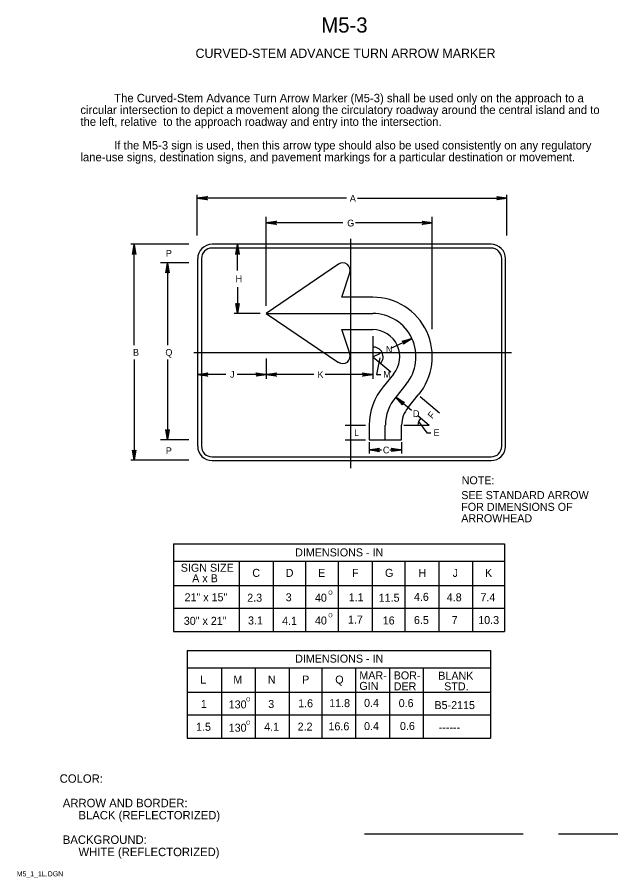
# Model space of a CAD drawing. Extents: x 0.5 to 7.5, y 0.2 to 10.2.
import ezdxf

# ---------------------------------------------------------------- set-up
doc = ezdxf.new("R2010")
doc.units = 0
for name, color, linetype in [('1', 7, 'Continuous'), ('2', 7, 'Continuous'), ('3', 7, 'Continuous')]:
    doc.layers.add(name, color=color, linetype=linetype)

# ---------------------------------------------------------------- blocks, each defined once
blk = doc.blocks.new('RARROW')
at = {"layer": '1'}
blk.add_lwpolyline([(-89.4, 11.2), (-86.1, 4.7), (0, 0), (-89.4, 11.2), (-94, 15.2), (0, 0), (-86, -4.3), (-89.2, -10.7), (0, 0), (-94, -14.9), (-89.2, -10.7)], dxfattribs=at)

msp = doc.modelspace()

# ---------------------------------------------------------------- linework, layer by layer
at = {"layer": '1'}
for p, q in [((4.545, 0.667), (6.395, 0.667)), ((6.809, 0.667), (7.5, 0.667))]:
    msp.add_line(p, q, dxfattribs=at)
at = {"layer": '2'}
for p, q in [((2.317, 4.054), (2.317, 3.032)), ((2.317, 4.054), (6.177, 4.054)), ((6.177, 4.056), (6.177, 3.032)), ((6.177, 3.849), (2.317, 3.849)), ((3.084, 3.848), (3.084, 3.03)), ((3.481, 3.849), (3.481, 3.032)), ((3.855, 3.849), (3.855, 3.032)), ((4.239, 3.849), (4.239, 3.032)), ((4.633, 3.849), (4.633, 3.032)), ((5.017, 3.849), (5.017, 3.032)), ((5.411, 3.849), (5.411, 3.032)), ((5.804, 3.849), (5.804, 3.032)), ((2.317, 3.57), (6.177, 3.57)), ((2.317, 3.304), (6.177, 3.304)), ((2.317, 3.032), (6.177, 3.032)), ((2.477, 2.81), (2.477, 1.786)), ((2.477, 2.81), (6.016, 2.81)), ((6.016, 2.81), (6.016, 1.786)), ((6.016, 2.603), (2.477, 2.603)), ((2.877, 2.603), (2.877, 1.786)), ((3.271, 2.603), (3.271, 1.786)), ((3.665, 2.603), (3.665, 1.786)), ((4.049, 2.603), (4.049, 1.786)), ((4.442, 2.603), (4.442, 1.786)), ((4.836, 2.603), (4.836, 1.786)), ((5.23, 2.603), (5.23, 1.786)), ((2.477, 2.324), (6.016, 2.324)), ((2.477, 2.058), (6.016, 2.058)), ((2.477, 1.786), (6.016, 1.786))]:
    msp.add_line(p, q, dxfattribs=at)
at = {"layer": '3'}
for p, q in [((2.594, 7.656), (2.594, 8.13)), ((4.335, 8.091), (2.594, 8.091)), ((4.465, 8.091), (6.206, 8.091)), ((6.206, 7.656), (6.206, 8.13)), ((3.399, 6.833), (3.399, 7.875)), ((5.336, 6.562), (5.336, 7.875)), ((4.292, 7.803), (3.399, 7.803)), ((5.336, 7.803), (4.439, 7.803)), ((2.495, 7.553), (1.821, 7.553)), ((1.858, 6.373), (1.858, 7.553)), ((6.022, 7.553), (2.767, 7.553)), ((3.189, 7.553), (3.026, 7.553)), ((3.064, 7.246), (3.064, 7.553)), ((4.385, 4.937), (4.385, 7.616)), ((6.022, 7.509), (2.767, 7.509)), ((2.495, 7.337), (2.166, 7.337)), ((2.246, 7.337), (2.246, 6.373)), ((2.598, 7.385), (2.598, 5.195)), ((2.643, 7.385), (2.643, 5.195)), ((6.147, 5.195), (6.147, 7.385)), ((6.191, 5.195), (6.191, 7.385)), ((4.24, 7.321), (3.399, 6.745)), ((4.281, 6.935), (4.373, 7.218)), ((3.064, 7.054), (3.064, 6.745)), ((4.641, 6.935), (4.281, 6.935)), ((3.327, 6.745), (3.026, 6.745)), ((3.399, 6.745), (4.641, 6.745)), ((3.399, 6.745), (4.24, 6.174)), ((4.373, 6.278), (4.28, 6.556)), ((4.28, 6.556), (4.641, 6.556)), ((4.641, 6.48), (4.641, 5.98)), ((4.852, 6.339), (5.099, 6.453)), ((2.555, 6.29), (6.261, 6.29)), ((4.641, 6.24), (4.731, 6.282)), ((4.641, 6.24), (4.851, 6.064)), ((1.858, 6.208), (1.858, 5.033)), ((2.246, 6.208), (2.246, 5.271)), ((3.399, 6.22), (3.399, 5.98)), ((2.926, 6.031), (2.598, 6.031)), ((3.399, 6.031), (3.061, 6.031)), ((3.953, 6.031), (3.399, 6.031)), ((4.641, 6.031), (4.086, 6.031)), ((4.883, 6.037), (4.764, 5.889)), ((5.028, 5.915), (4.909, 5.768)), ((4.909, 5.768), (5.092, 5.614)), ((5.054, 5.646), (5.173, 5.793)), ((5.196, 5.775), (5.42, 5.586)), ((5.171, 5.548), (5.3, 5.44)), ((4.321, 5.44), (4.556, 5.44)), ((4.599, 5.44), (4.599, 5.271)), ((4.788, 5.271), (4.788, 5.44)), ((4.978, 5.271), (4.978, 5.44)), ((5.003, 5.44), (5.3, 5.44)), ((2.495, 5.271), (2.166, 5.271)), ((4.321, 5.271), (4.556, 5.271)), ((4.599, 5.271), (4.978, 5.271)), ((4.599, 5.241), (4.599, 5.11)), ((4.978, 5.241), (4.978, 5.11)), ((4.599, 5.151), (4.742, 5.151)), ((4.842, 5.151), (4.978, 5.151)), ((2.495, 5.033), (1.821, 5.033)), ((2.767, 5.071), (6.022, 5.071)), ((2.767, 5.027), (6.022, 5.027))]:
    msp.add_line(p, q, dxfattribs=at)
for points in [[(4.726, 6.227), (4.687, 6.032), (4.736, 6.032)], [(5.176, 5.485), (5.271, 5.352), (5.32, 5.352)]]:
    msp.add_lwpolyline(points, dxfattribs=at)
for centre, radius, start, end in [((2.767, 7.385), 0.168, 90, 180), ((6.022, 7.385), 0.168, 0, 90), ((2.767, 7.385), 0.124, 90, 180), ((6.022, 7.385), 0.124, 0, 90), ((4.291, 7.249), 0.088, 339.2037, 125.0464), ((4.641, 6.24), 0.695, 320, 90), ((4.641, 6.24), 0.505, 320, 90), ((4.641, 6.24), 0.316, 320, 90), ((4.647, 6.238), 0.115, 319.152, 92.74), ((4.291, 6.247), 0.088, 234.9536, 20.7963), ((5.294, 5.44), 0.695, 139.6818, 180), ((5.294, 5.44), 0.505, 139.5625, 180), ((5.294, 5.44), 0.316, 139.2999, 180), ((5.265, 5.448), 0.0966, 130.7799, 185.0153), ((2.767, 5.195), 0.168, 180, 270), ((2.767, 5.195), 0.124, 180, 270), ((6.022, 5.195), 0.168, 270, 0), ((6.022, 5.195), 0.124, 270, 0)]:
    msp.add_arc(centre, radius, start, end, dxfattribs=at)

# ---------------------------------------------------------------- block references
for p, xscale, yscale, rotation in [((2.594, 8.091), 0.0012568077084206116, 0.0013084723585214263, 180), ((3.399, 7.803), 0.001256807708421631, 0.0013084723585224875, 180), ((1.858, 7.552), 0.001256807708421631, 0.0013084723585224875, 90), ((3.064, 7.553), 0.001256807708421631, 0.0013084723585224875, 90), ((2.246, 7.337), 0.001256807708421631, 0.0013084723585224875, 90), ((3.064, 6.744), 0.001256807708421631, 0.0013084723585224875, -90), ((5.099, 6.453), 0.001256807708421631, 0.0013084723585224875, 25.00000000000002), ((2.598, 6.031), 0.001256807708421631, 0.0013084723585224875, 180), ((3.399, 6.031), 0.001256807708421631, 0.0013084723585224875, 180), ((4.909, 5.768), 0.001256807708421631, 0.0013084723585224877, 139.99999999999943), ((2.246, 5.271), 0.001256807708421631, 0.0013084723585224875, -90), ((1.858, 5.032), 0.001256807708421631, 0.0013084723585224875, -90), ((4.599, 5.151), 0.001256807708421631, 0.0013084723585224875, 180)]:
    msp.add_blockref('RARROW', p, dxfattribs=dict(at, xscale=xscale, yscale=yscale, rotation=rotation))
for p, xscale, yscale in [((6.206, 8.091), 0.0012568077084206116, 0.0013084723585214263), ((5.336, 7.803), 0.001256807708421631, 0.0013084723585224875), ((3.399, 6.031), 0.001256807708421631, 0.0013084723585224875), ((4.641, 6.031), 0.001256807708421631, 0.0013084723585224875), ((4.978, 5.151), 0.001256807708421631, 0.0013084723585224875)]:
    msp.add_blockref('RARROW', p, dxfattribs=dict(at, xscale=xscale, yscale=yscale))

# ---------------------------------------------------------------- texts
at = {"layer": '1'}
for s, height, p in [('M5-3', 0.1772, (4.041, 10.025)), ('CURVED-STEM ADVANCE TURN ARROW MARKER', 0.10828, (2.574, 9.729)), ('COLOR:', 0.0984, (0.989, 1.265)), (' ARROW AND BORDER:', 0.09842, (0.989, 0.979)), ('      BLACK (REFLECTORIZED)', 0.09842, (0.989, 0.837)), (' BACKGROUND:', 0.09842, (0.989, 0.551)), ('      WHITE (REFLECTORIZED)', 0.09842, (0.989, 0.408)), ('M5_1_1L.DGN', 0.05906, (0.487, 0.172))]:
    msp.add_text(s, height=height, dxfattribs=at).set_placement(p)
at = {"layer": '2'}
for s, height, p in [('The Curved-Stem Advance Turn Arrow Marker (M5-3) shall be used only on the approach to a ', 0.09842, (1.625, 9.211)), ('circular intersection to depict a movement along the circulatory roadway around the central island and to ', 0.098415, (1.231, 9.074)), ('the left, relative  to the approach roadway and entry into the intersection.', 0.09842, (1.231, 8.936)), ('If the M5-3 sign is used, then this arrow type should also be used consistently on any regulatory ', 0.09842, (1.625, 8.66)), ('lane-use signs, destination signs, and pavement markings for a particular destination or movement.', 0.09842, (1.231, 8.522)), ('NOTE:', 0.0935, (5.679, 4.75)), ('SEE STANDARD ARROW', 0.09351, (5.674, 4.577)), ('FOR DIMENSIONS OF', 0.09351, (5.674, 4.44)), ('ARROWHEAD', 0.0935, (5.674, 4.307)), ('DIMENSIONS - IN', 0.09351, (3.736, 3.908)), ('SIGN SIZE', 0.0935, (2.402, 3.729)), ('C', 0.0935, (3.236, 3.669)), ('D', 0.0935, (3.626, 3.669)), ('E', 0.0935, (4.004, 3.669)), ('F', 0.0935, (4.399, 3.669)), ('G', 0.0935, (4.784, 3.669)), ('H', 0.0935, (5.173, 3.669)), ('J', 0.0935, (5.573, 3.669)), ('K', 0.0935, (5.951, 3.669)), ('A x B', 0.0935, (2.535, 3.606)), ('21" x 15"', 0.0935, (2.446, 3.384)), ('2.3', 0.0935, (3.177, 3.379)), ('3', 0.0935, (3.626, 3.384)), ('40', 0.0935, (3.967, 3.379)), ('O', 0.0468, (4.123, 3.462)), ('1.1', 0.0935, (4.361, 3.384)), ('11.5', 0.0935, (4.711, 3.379)), ('4.6', 0.0935, (5.122, 3.389)), ('4.8', 0.0935, (5.505, 3.384)), ('7.4', 0.0935, (5.898, 3.384)), ('O', 0.0468, (4.123, 3.197)), ('1.7', 0.0935, (4.352, 3.123)), ('30" x 21"', 0.0935, (2.437, 3.109)), ('3.1', 0.0935, (3.186, 3.113)), ('4.1', 0.0935, (3.584, 3.109)), ('40', 0.0935, (3.967, 3.113)), ('16', 0.0935, (4.758, 3.113)), ('6.5', 0.0935, (5.122, 3.118)), ('7', 0.0935, (5.562, 3.118)), ('10.3', 0.0935, (5.872, 3.118)), ('DIMENSIONS - IN', 0.09351, (3.736, 2.668)), ('L', 0.0935, (2.629, 2.423)), ('M', 0.0935, (3.015, 2.423)), ('N', 0.0935, (3.417, 2.423)), ('P', 0.0935, (3.818, 2.423)), ('Q', 0.0935, (4.204, 2.423)), ('MAR-', 0.0935, (4.485, 2.472)), ('BOR-', 0.0935, (4.886, 2.472)), ('BLANK', 0.0935, (5.406, 2.468)), ('GIN', 0.0935, (4.485, 2.349)), ('DER', 0.0935, (4.886, 2.344)), ('STD.', 0.0935, (5.475, 2.344)), ('1', 0.0935, (2.636, 2.138)), ('130', 0.0935, (2.961, 2.133)), ('O', 0.0468, (3.164, 2.216)), ('3', 0.0935, (3.422, 2.138)), ('1.6', 0.0935, (3.771, 2.146)), ('11.8', 0.0935, (4.133, 2.148)), ('0.4', 0.0935, (4.54, 2.151)), ('0.6', 0.0935, (4.944, 2.148)), ('B5-2115', 0.0935, (5.361, 2.125)), ('1.5', 0.0935, (2.58, 1.872)), ('130', 0.0935, (2.961, 1.861)), ('O', 0.0468, (3.164, 1.944)), ('4.1', 0.0935, (3.375, 1.872)), ('2.2', 0.0935, (3.765, 1.874)), ('16.6', 0.0935, (4.125, 1.877)), ('0.4', 0.0935, (4.54, 1.88)), ('0.6', 0.0935, (4.959, 1.881)), ('------', 0.0935, (5.411, 1.865))]:
    msp.add_text(s, height=height, dxfattribs=at).set_placement(p)
at = {"layer": '3'}
for s, height, p in [('A', 0.0787, (4.374, 8.051)), ('G', 0.0787, (4.343, 7.761)), ('P', 0.0787, (2.227, 7.408)), ('H', 0.0787, (3.041, 7.11)), ('N', 0.0787, (4.794, 6.286)), ('B', 0.0788, (1.844, 6.251)), ('Q', 0.0787, (2.222, 6.251)), ('J', 0.0787, (2.976, 5.995)), ('K', 0.0787, (3.997, 5.992)), ('M', 0.0787, (4.764, 5.995)), ('D', 0.0787, (5.11, 5.537)), ('L', 0.0787, (4.424, 5.315)), ('E', 0.0787, (5.35, 5.315)), ('P', 0.0787, (2.227, 5.103)), ('C', 0.0787, (4.76, 5.111))]:
    msp.add_text(s, height=height, dxfattribs=at).set_placement(p)
msp.add_text('F', height=0.0787, rotation=50.1944, dxfattribs=at).set_placement((5.335, 5.509))

doc.saveas('drawing.dxf')
